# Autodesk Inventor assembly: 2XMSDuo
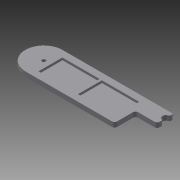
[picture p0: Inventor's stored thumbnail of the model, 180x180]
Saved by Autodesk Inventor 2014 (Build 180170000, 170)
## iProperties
Created: 2015-01
Part Number: 2XMSDuo
Document SubType Name: Assembly
Designer: Drano
Author: Drano
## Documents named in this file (3)
- C:\Users\Drano\Documents\SD swiss army\2XMSDuo.iam
- C:\Users\Drano\Documents\SD swiss army\2XMSduo.ipt
- C:\Users\Drano\Documents\SD swiss army\backplate.ipt
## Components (2 placed, 2 different names)
1. backplate:1 — Mate:1, Mate:2, Flush:1
2. 2XMSduo:1 — Mate:1, Mate:2, Flush:1
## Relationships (3: Mate 2, Flush 1)
- Mate:1: backplate:1 ↔ 2XMSduo:1
- Mate:2: backplate:1 ↔ 2XMSduo:1
- Flush:1: backplate:1 ↔ 2XMSduo:1
